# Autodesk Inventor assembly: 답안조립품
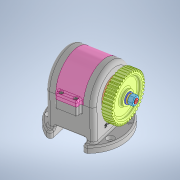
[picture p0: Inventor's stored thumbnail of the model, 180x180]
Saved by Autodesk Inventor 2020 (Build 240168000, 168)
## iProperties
Created: 2024-08
Part Number: 답안조립품
Document SubType Name: Assembly
Designer: oem
Author: oem
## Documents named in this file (21)
- C:\Users\oem\Desktop\740804V1015\답안조립품.iam
- C:\Users\oem\Desktop\740804V1015\본체.ipt
- C:\Users\oem\Documents\Inventor\E형 멈춤링 10-8.ipt
- C:\Users\oem\Desktop\740804V1015\가져온 구성요소\깊은 홈 볼 베어링 6904\깊은 홈 볼 베어링 6904.ipt
- C:\Users\oem\Desktop\740804V1015\가져온 구성요소\뒷커버\뒷커버.ipt
- C:\Users\oem\Desktop\740804V1015\가져온 구성요소\링크\링크.ipt
- C:\Users\oem\Desktop\740804V1015\가져온 구성요소\부시 커버\부시 커버.ipt
- C:\Users\oem\Desktop\740804V1015\가져온 구성요소\스퍼 기어\스퍼 기어.ipt
- C:\Users\oem\Desktop\740804V1015\가져온 구성요소\스프링 와셔 M10\스프링 와셔 M10.ipt
- C:\Users\oem\Desktop\740804V1015\가져온 구성요소\앞커버\앞커버.ipt
- C:\Users\oem\Desktop\740804V1015\가져온 구성요소\오일레스 부시 20 15\오일레스 부시 20 15.ipt
- C:\Users\oem\Desktop\740804V1015\가져온 구성요소\오일실 20 32 5\오일실 20 32 5.ipt
- C:\Users\oem\Desktop\740804V1015\가져온 구성요소\윗커버\윗커버.ipt
- C:\Users\oem\Desktop\740804V1015\가져온 구성요소\육각 너트 M10x1\육각 너트 M10x1.ipt
- C:\Users\oem\Desktop\740804V1015\가져온 구성요소\육각 소켓 머리 볼트 M4x10\육각 소켓 머리 볼트 M4x10.ipt
- C:\Users\oem\Desktop\740804V1015\가져온 구성요소\칼라\칼라.ipt
- C:\Users\oem\Desktop\740804V1015\가져온 구성요소\펀치\펀치.ipt
- C:\Users\oem\Desktop\740804V1015\가져온 구성요소\편심축\편심축.ipt
- C:\Users\oem\Desktop\740804V1015\가져온 구성요소\평와셔 M10\평와셔 M10.ipt
- C:\Users\oem\Desktop\740804V1015\가져온 구성요소\평행키 5x5x12\평행키 5x5x12.ipt
- C:\Users\oem\Desktop\740804V1015\가져온 구성요소\핀\핀.ipt
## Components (2 placed, 2 different names)
1. E형 멈춤링 10-8:1
2. 핀:1
